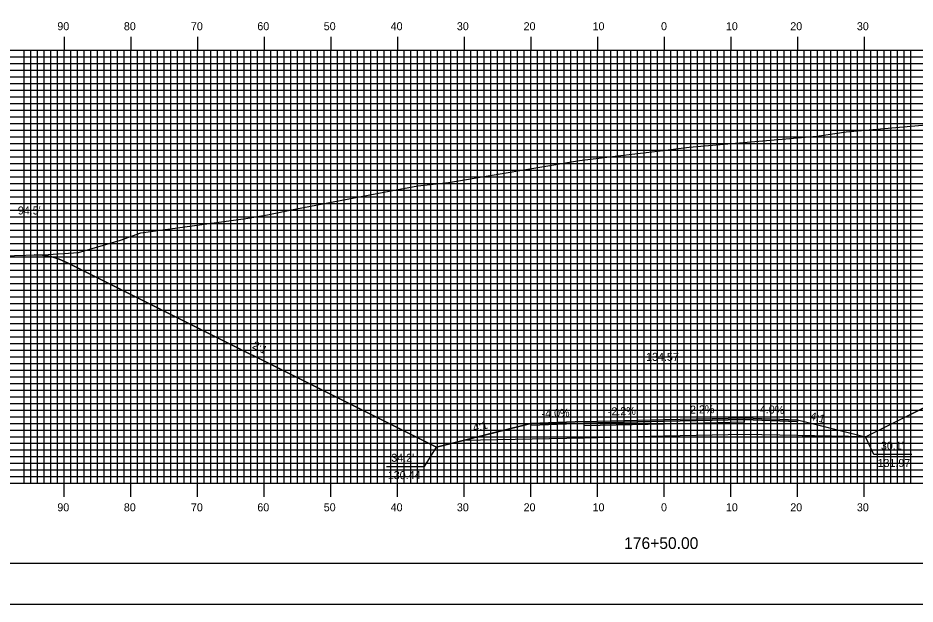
# Model space of a CAD drawing. Extents: x 1784615 to 1784958, y 442591 to 442811.
# Drawn here: x 1784683.6 to 1784818.1, y 442590.5 to 442678.5 of the extents above; entities that cross this region are included whole.
import ezdxf

# ---------------------------------------------------------------- set-up
doc = ezdxf.new("R2010")
doc.units = 0
for name, color, linetype in [('ANNOTATION', 7, 'Continuous'), ('BORDER', 7, 'Continuous'), ('D_Roadway_Centerline', 7, 'Continuous'), ('D_Roadway_Centerline_Text', 7, 'Continuous'), ('D_Roadway_Edge_Shoulder', 7, 'Continuous'), ('D_Roadway_Edge_TW', 7, 'Continuous'), ('D_Roadway_Pavement', 7, 'Continuous'), ('D_Roadway_SlopeLines', 7, 'Continuous'), ('D_Roadway_SubGrade', 7, 'Continuous'), ('D_Text_Standard', 7, 'Continuous'), ('H_V ANNOTATION', 7, 'Continuous'), ('MAJOR', 7, 'Continuous'), ('MINOR', 7, 'Continuous'), ('PLOT BOUNDARY', 7, 'Continuous'), ('S_Roadway_Centerline', 7, 'Continuous')]:
    doc.layers.add(name, color=color, linetype=linetype)

msp = doc.modelspace()

# ---------------------------------------------------------------- linework, layer by layer
at = {"layer": 'ANNOTATION'}
for points in [[(1784817.65, 442613), (1784811.96, 442613), (1784810.69, 442615.64)], [(1784738.83, 442611.17), (1784744.53, 442611.17), (1784746.34, 442614.11)]]:
    msp.add_lwpolyline(points, dxfattribs=at)
at = {"layer": 'BORDER'}
msp.add_lwpolyline([(1784630.91, 442596.67), (1784950.91, 442596.67), (1784950.91, 442806.67), (1784630.91, 442806.67)], close=True, dxfattribs=at)
at = {"layer": 'D_Roadway_Centerline'}
msp.add_lwpolyline([(1784685.99, 442642.94), (1784687.24, 442642.9), (1784688.49, 442642.7), (1784689.74, 442642.32), (1784690.99, 442641.78), (1784746.34, 442614.11), (1784750.34, 442615.11), (1784760.51, 442617.65), (1784768.51, 442617.97), (1784780.51, 442618.24), (1784792.51, 442618.5), (1784800.51, 442618.18), (1784810.69, 442615.64), (1784902.15, 442661.37)], dxfattribs=at)
at = {"layer": 'D_Roadway_Edge_Shoulder'}
for points in [[(1784768.51, 442617.97), (1784760.51, 442617.65), (1784760.51, 442617.4), (1784768.51, 442617.72)], [(1784792.51, 442618.5), (1784800.51, 442618.18), (1784800.51, 442617.93), (1784792.51, 442618.25)]]:
    msp.add_lwpolyline(points, close=True, dxfattribs=at)
at = {"layer": 'D_Roadway_Edge_TW'}
msp.add_lwpolyline([(1784768.51, 442617.72), (1784768.51, 442617.97), (1784780.51, 442618.24), (1784792.51, 442618.5), (1784792.51, 442618.25), (1784780.51, 442617.99)], close=True, dxfattribs=at)
at = {"layer": 'D_Roadway_Pavement'}
msp.add_lwpolyline([(1784768.51, 442617.3), (1784768.51, 442617.72), (1784780.51, 442617.99), (1784792.51, 442618.25), (1784792.51, 442617.83), (1784780.51, 442617.57)], close=True, dxfattribs=at)
at = {"layer": 'D_Roadway_SlopeLines'}
for p, q in [((1784812.69, 442616.64), (1784902.15, 442661.37)), ((1784800.51, 442618.18), (1784810.69, 442615.64)), ((1784810.69, 442615.64), (1784812.69, 442616.64)), ((1784801.22, 442615.83), (1784810.69, 442615.64))]:
    msp.add_line(p, q, dxfattribs=at)
for points in [[(1784746.34, 442614.11), (1784690.99, 442641.78), (1784689.74, 442642.32), (1784688.49, 442642.7), (1784687.24, 442642.9), (1784685.99, 442642.94)], [(1784800.51, 442618.18), (1784805.13, 442617.03)], [(1784760.51, 442617.65), (1784746.34, 442614.11)]]:
    msp.add_lwpolyline(points, dxfattribs=at)
at = {"layer": 'D_Roadway_SubGrade'}
msp.add_lwpolyline([(1784768.51, 442615.47), (1784750.34, 442615.11), (1784760.51, 442617.65), (1784760.51, 442617.4), (1784768.51, 442617.72), (1784780.51, 442617.99), (1784792.51, 442618.25), (1784800.51, 442617.93), (1784800.51, 442618.18), (1784810.69, 442615.64), (1784800.51, 442615.84), (1784792.51, 442616), (1784780.51, 442615.74)], close=True, dxfattribs=at)
at = {"layer": 'MAJOR'}
for p, q in [((1784690.51, 442675.67), (1784690.51, 442673.67)), ((1784700.51, 442675.67), (1784700.51, 442673.67)), ((1784710.51, 442675.67), (1784710.51, 442673.67)), ((1784720.51, 442675.67), (1784720.51, 442673.67)), ((1784730.51, 442675.67), (1784730.51, 442673.67)), ((1784740.51, 442675.67), (1784740.51, 442673.67)), ((1784750.51, 442675.67), (1784750.51, 442673.67)), ((1784760.51, 442675.67), (1784760.51, 442673.67)), ((1784770.51, 442675.67), (1784770.51, 442673.67)), ((1784780.51, 442675.67), (1784780.51, 442673.67)), ((1784790.51, 442675.67), (1784790.51, 442673.67)), ((1784800.51, 442675.67), (1784800.51, 442673.67)), ((1784810.51, 442675.67), (1784810.51, 442673.67)), ((1784640.51, 442673.67), (1784920.51, 442673.67)), ((1784640.51, 442673.67), (1784920.51, 442673.67)), ((1784690.51, 442608.67), (1784690.51, 442673.67)), ((1784700.51, 442608.67), (1784700.51, 442673.67)), ((1784710.51, 442608.67), (1784710.51, 442673.67)), ((1784720.51, 442608.67), (1784720.51, 442673.67)), ((1784730.51, 442608.67), (1784730.51, 442673.67)), ((1784740.51, 442608.67), (1784740.51, 442673.67)), ((1784750.51, 442608.67), (1784750.51, 442673.67)), ((1784760.51, 442608.67), (1784760.51, 442673.67)), ((1784770.51, 442608.67), (1784770.51, 442673.67)), ((1784780.51, 442608.67), (1784780.51, 442673.67)), ((1784790.51, 442608.67), (1784790.51, 442673.67)), ((1784800.51, 442608.67), (1784800.51, 442673.67)), ((1784810.51, 442608.67), (1784810.51, 442673.67)), ((1784640.51, 442668.67), (1784920.51, 442668.67)), ((1784640.51, 442663.67), (1784920.51, 442663.67)), ((1784640.51, 442658.67), (1784920.51, 442658.67)), ((1784640.51, 442653.67), (1784920.51, 442653.67)), ((1784640.51, 442648.67), (1784920.51, 442648.67)), ((1784640.51, 442643.67), (1784920.51, 442643.67)), ((1784640.51, 442638.67), (1784920.51, 442638.67)), ((1784640.51, 442633.67), (1784920.51, 442633.67)), ((1784640.51, 442628.67), (1784920.51, 442628.67)), ((1784640.51, 442623.67), (1784920.51, 442623.67)), ((1784640.51, 442618.67), (1784920.51, 442618.67)), ((1784640.51, 442613.67), (1784920.51, 442613.67)), ((1784640.51, 442608.67), (1784920.51, 442608.67)), ((1784690.51, 442606.66), (1784690.51, 442608.67)), ((1784700.51, 442606.66), (1784700.51, 442608.67)), ((1784710.51, 442606.66), (1784710.51, 442608.67)), ((1784720.51, 442606.66), (1784720.51, 442608.67)), ((1784730.51, 442606.66), (1784730.51, 442608.67)), ((1784740.51, 442606.66), (1784740.51, 442608.67)), ((1784750.51, 442606.66), (1784750.51, 442608.67)), ((1784760.51, 442606.66), (1784760.51, 442608.67)), ((1784770.51, 442606.66), (1784770.51, 442608.67)), ((1784780.51, 442606.66), (1784780.51, 442608.67)), ((1784790.51, 442606.66), (1784790.51, 442608.67)), ((1784800.51, 442606.66), (1784800.51, 442608.67)), ((1784810.51, 442606.66), (1784810.51, 442608.67))]:
    msp.add_line(p, q, dxfattribs=at)
at = {"layer": 'MINOR'}
for p, q in [((1784684.51, 442608.67), (1784684.51, 442673.67)), ((1784685.51, 442608.67), (1784685.51, 442673.67)), ((1784686.51, 442608.67), (1784686.51, 442673.67)), ((1784687.51, 442608.67), (1784687.51, 442673.67)), ((1784688.51, 442608.67), (1784688.51, 442673.67)), ((1784689.51, 442608.67), (1784689.51, 442673.67)), ((1784691.51, 442608.67), (1784691.51, 442673.67)), ((1784692.51, 442608.67), (1784692.51, 442673.67)), ((1784693.51, 442608.67), (1784693.51, 442673.67)), ((1784694.51, 442608.67), (1784694.51, 442673.67)), ((1784695.51, 442608.67), (1784695.51, 442673.67)), ((1784696.51, 442608.67), (1784696.51, 442673.67)), ((1784697.51, 442608.67), (1784697.51, 442673.67)), ((1784698.51, 442608.67), (1784698.51, 442673.67)), ((1784699.51, 442608.67), (1784699.51, 442673.67)), ((1784701.51, 442608.67), (1784701.51, 442673.67)), ((1784702.51, 442608.67), (1784702.51, 442673.67)), ((1784703.51, 442608.67), (1784703.51, 442673.67)), ((1784704.51, 442608.67), (1784704.51, 442673.67)), ((1784705.51, 442608.67), (1784705.51, 442673.67)), ((1784706.51, 442608.67), (1784706.51, 442673.67)), ((1784707.51, 442608.67), (1784707.51, 442673.67)), ((1784708.51, 442608.67), (1784708.51, 442673.67)), ((1784709.51, 442608.67), (1784709.51, 442673.67)), ((1784711.51, 442608.67), (1784711.51, 442673.67)), ((1784712.51, 442608.67), (1784712.51, 442673.67)), ((1784713.51, 442608.67), (1784713.51, 442673.67)), ((1784714.51, 442608.67), (1784714.51, 442673.67)), ((1784715.51, 442608.67), (1784715.51, 442673.67)), ((1784716.51, 442608.67), (1784716.51, 442673.67)), ((1784717.51, 442608.67), (1784717.51, 442673.67)), ((1784718.51, 442608.67), (1784718.51, 442673.67)), ((1784719.51, 442608.67), (1784719.51, 442673.67)), ((1784721.51, 442608.67), (1784721.51, 442673.67)), ((1784722.51, 442608.67), (1784722.51, 442673.67)), ((1784723.51, 442608.67), (1784723.51, 442673.67)), ((1784724.51, 442608.67), (1784724.51, 442673.67)), ((1784725.51, 442608.67), (1784725.51, 442673.67)), ((1784726.51, 442608.67), (1784726.51, 442673.67)), ((1784727.51, 442608.67), (1784727.51, 442673.67)), ((1784728.51, 442608.67), (1784728.51, 442673.67)), ((1784729.51, 442608.67), (1784729.51, 442673.67)), ((1784731.51, 442608.67), (1784731.51, 442673.67)), ((1784732.51, 442608.67), (1784732.51, 442673.67)), ((1784733.51, 442608.67), (1784733.51, 442673.67)), ((1784734.51, 442608.67), (1784734.51, 442673.67)), ((1784735.51, 442608.67), (1784735.51, 442673.67)), ((1784736.51, 442608.67), (1784736.51, 442673.67)), ((1784737.51, 442608.67), (1784737.51, 442673.67)), ((1784738.51, 442608.67), (1784738.51, 442673.67)), ((1784739.51, 442608.67), (1784739.51, 442673.67)), ((1784741.51, 442608.67), (1784741.51, 442673.67)), ((1784742.51, 442608.67), (1784742.51, 442673.67)), ((1784743.51, 442608.67), (1784743.51, 442673.67)), ((1784744.51, 442608.67), (1784744.51, 442673.67)), ((1784745.51, 442608.67), (1784745.51, 442673.67)), ((1784746.51, 442608.67), (1784746.51, 442673.67)), ((1784747.51, 442608.67), (1784747.51, 442673.67)), ((1784748.51, 442608.67), (1784748.51, 442673.67)), ((1784749.51, 442608.67), (1784749.51, 442673.67)), ((1784751.51, 442608.67), (1784751.51, 442673.67)), ((1784752.51, 442608.67), (1784752.51, 442673.67)), ((1784753.51, 442608.67), (1784753.51, 442673.67)), ((1784754.51, 442608.67), (1784754.51, 442673.67)), ((1784755.51, 442608.67), (1784755.51, 442673.67)), ((1784756.51, 442608.67), (1784756.51, 442673.67)), ((1784757.51, 442608.67), (1784757.51, 442673.67)), ((1784758.51, 442608.67), (1784758.51, 442673.67)), ((1784759.51, 442608.67), (1784759.51, 442673.67)), ((1784761.51, 442608.67), (1784761.51, 442673.67)), ((1784762.51, 442608.67), (1784762.51, 442673.67)), ((1784763.51, 442608.67), (1784763.51, 442673.67)), ((1784764.51, 442608.67), (1784764.51, 442673.67)), ((1784765.51, 442608.67), (1784765.51, 442673.67)), ((1784766.51, 442608.67), (1784766.51, 442673.67)), ((1784767.51, 442608.67), (1784767.51, 442673.67)), ((1784768.51, 442608.67), (1784768.51, 442673.67)), ((1784769.51, 442608.67), (1784769.51, 442673.67)), ((1784771.51, 442608.67), (1784771.51, 442673.67)), ((1784772.51, 442608.67), (1784772.51, 442673.67)), ((1784773.51, 442608.67), (1784773.51, 442673.67)), ((1784774.51, 442608.67), (1784774.51, 442673.67)), ((1784775.51, 442608.67), (1784775.51, 442673.67)), ((1784776.51, 442608.67), (1784776.51, 442673.67)), ((1784777.51, 442608.67), (1784777.51, 442673.67)), ((1784778.51, 442608.67), (1784778.51, 442673.67)), ((1784779.51, 442608.67), (1784779.51, 442673.67)), ((1784781.51, 442608.67), (1784781.51, 442673.67)), ((1784782.51, 442608.67), (1784782.51, 442673.67)), ((1784783.51, 442608.67), (1784783.51, 442673.67)), ((1784784.51, 442608.67), (1784784.51, 442673.67)), ((1784785.51, 442608.67), (1784785.51, 442673.67)), ((1784786.51, 442608.67), (1784786.51, 442673.67)), ((1784787.51, 442608.67), (1784787.51, 442673.67)), ((1784788.51, 442608.67), (1784788.51, 442673.67)), ((1784789.51, 442608.67), (1784789.51, 442673.67)), ((1784791.51, 442608.67), (1784791.51, 442673.67)), ((1784792.51, 442608.67), (1784792.51, 442673.67)), ((1784793.51, 442608.67), (1784793.51, 442673.67)), ((1784794.51, 442608.67), (1784794.51, 442673.67)), ((1784795.51, 442608.67), (1784795.51, 442673.67)), ((1784796.51, 442608.67), (1784796.51, 442673.67)), ((1784797.51, 442608.67), (1784797.51, 442673.67)), ((1784798.51, 442608.67), (1784798.51, 442673.67)), ((1784799.51, 442608.67), (1784799.51, 442673.67)), ((1784801.51, 442608.67), (1784801.51, 442673.67)), ((1784802.51, 442608.67), (1784802.51, 442673.67)), ((1784803.51, 442608.67), (1784803.51, 442673.67)), ((1784804.51, 442608.67), (1784804.51, 442673.67)), ((1784805.51, 442608.67), (1784805.51, 442673.67)), ((1784806.51, 442608.67), (1784806.51, 442673.67)), ((1784807.51, 442608.67), (1784807.51, 442673.67)), ((1784808.51, 442608.67), (1784808.51, 442673.67)), ((1784809.51, 442608.67), (1784809.51, 442673.67)), ((1784811.51, 442608.67), (1784811.51, 442673.67)), ((1784812.51, 442608.67), (1784812.51, 442673.67)), ((1784813.51, 442608.67), (1784813.51, 442673.67)), ((1784814.51, 442608.67), (1784814.51, 442673.67)), ((1784815.51, 442608.67), (1784815.51, 442673.67)), ((1784816.51, 442608.67), (1784816.51, 442673.67)), ((1784817.51, 442608.67), (1784817.51, 442673.67)), ((1784640.51, 442672.67), (1784920.51, 442672.67)), ((1784640.51, 442671.67), (1784920.51, 442671.67)), ((1784640.51, 442670.67), (1784920.51, 442670.67)), ((1784640.51, 442669.67), (1784920.51, 442669.67)), ((1784640.51, 442667.67), (1784920.51, 442667.67)), ((1784640.51, 442666.67), (1784920.51, 442666.67)), ((1784640.51, 442665.67), (1784920.51, 442665.67)), ((1784640.51, 442664.67), (1784920.51, 442664.67)), ((1784640.51, 442662.67), (1784920.51, 442662.67)), ((1784640.51, 442661.67), (1784920.51, 442661.67)), ((1784640.51, 442660.67), (1784920.51, 442660.67)), ((1784640.51, 442659.67), (1784920.51, 442659.67)), ((1784640.51, 442657.67), (1784920.51, 442657.67)), ((1784640.51, 442656.67), (1784920.51, 442656.67)), ((1784640.51, 442655.67), (1784920.51, 442655.67)), ((1784640.51, 442654.67), (1784920.51, 442654.67)), ((1784640.51, 442652.67), (1784920.51, 442652.67)), ((1784640.51, 442651.67), (1784920.51, 442651.67)), ((1784640.51, 442650.67), (1784920.51, 442650.67)), ((1784640.51, 442649.67), (1784920.51, 442649.67)), ((1784640.51, 442647.67), (1784920.51, 442647.67)), ((1784640.51, 442646.67), (1784920.51, 442646.67)), ((1784640.51, 442645.67), (1784920.51, 442645.67)), ((1784640.51, 442644.67), (1784920.51, 442644.67)), ((1784640.51, 442642.67), (1784920.51, 442642.67)), ((1784640.51, 442641.67), (1784920.51, 442641.67)), ((1784640.51, 442640.67), (1784920.51, 442640.67)), ((1784640.51, 442639.67), (1784920.51, 442639.67)), ((1784640.51, 442637.67), (1784920.51, 442637.67)), ((1784640.51, 442636.67), (1784920.51, 442636.67)), ((1784640.51, 442635.67), (1784920.51, 442635.67)), ((1784640.51, 442634.67), (1784920.51, 442634.67)), ((1784640.51, 442632.67), (1784920.51, 442632.67)), ((1784640.51, 442631.67), (1784920.51, 442631.67)), ((1784640.51, 442630.67), (1784920.51, 442630.67)), ((1784640.51, 442629.67), (1784920.51, 442629.67)), ((1784640.51, 442627.67), (1784920.51, 442627.67)), ((1784640.51, 442626.67), (1784920.51, 442626.67)), ((1784640.51, 442625.67), (1784920.51, 442625.67)), ((1784640.51, 442624.67), (1784920.51, 442624.67)), ((1784640.51, 442622.67), (1784920.51, 442622.67)), ((1784640.51, 442621.67), (1784920.51, 442621.67)), ((1784640.51, 442620.67), (1784920.51, 442620.67)), ((1784640.51, 442619.67), (1784920.51, 442619.67)), ((1784640.51, 442617.67), (1784920.51, 442617.67)), ((1784640.51, 442616.67), (1784920.51, 442616.67)), ((1784640.51, 442615.67), (1784920.51, 442615.67)), ((1784640.51, 442614.67), (1784920.51, 442614.67)), ((1784640.51, 442612.67), (1784920.51, 442612.67)), ((1784640.51, 442611.67), (1784920.51, 442611.67)), ((1784640.51, 442610.67), (1784920.51, 442610.67)), ((1784640.51, 442609.67), (1784920.51, 442609.67))]:
    msp.add_line(p, q, dxfattribs=at)
at = {"layer": 'PLOT BOUNDARY'}
msp.add_lwpolyline([(1784614.73, 442590.55), (1784954.73, 442590.55), (1784954.73, 442810.55), (1784614.73, 442810.55)], close=True, dxfattribs=at)
at = {"layer": 'S_Roadway_Centerline'}
msp.add_lwpolyline([(1784681.37, 442642.79), (1784688.11, 442643), (1784692.65, 442643.32), (1784698.98, 442645.18), (1784702, 442646.28), (1784717.77, 442648.43), (1784720.98, 442648.95), (1784725.1, 442649.79), (1784739.5, 442652.58), (1784743.57, 442653.31), (1784748.13, 442653.84), (1784767.78, 442657.1), (1784774.41, 442657.93), (1784779.5, 442658.54), (1784784.27, 442659.12), (1784803.42, 442660.79), (1784807.8, 442661.4), (1784823.23, 442662.76)], dxfattribs=at)

# ---------------------------------------------------------------- texts
at = {"layer": 'ANNOTATION'}
for s, rotation, p in [('2:1', 333.4349, (1784718.6, 442629.01)), ('-4.0%', 2.2906, (1784762.14, 442618.52)), ('-2.2%', 1.2603, (1784772.07, 442618.85)), ('2.2%', 1.2603, (1784784.39, 442619.12)), ('-4.0%', 357.7094, (1784794.3, 442619.23)), ('4:1', 345.9638, (1784802.3, 442618.24)), ('4:1', 14.0362, (1784751.96, 442616.38))]:
    msp.add_text(s, height=1.2, rotation=rotation, dxfattribs=at).set_placement(p)
for s, p in [("30.1'", (1784813.01, 442613.72)), ("34.2'", (1784739.57, 442611.9)), ('131.97', (1784812.51, 442611.12)), ('130.44', (1784739.05, 442609.3))]:
    msp.add_text(s, height=1.2, dxfattribs=at).set_placement(p)
at = {"layer": 'D_Roadway_Centerline'}
for s, p in [('C', (1784780.51, 442618.24)), ('L', (1784780.51, 442618.23))]:
    msp.add_text(s, height=0.0146, dxfattribs=at).set_placement(p)
at = {"layer": 'D_Roadway_Centerline_Text'}
msp.add_text('134.57', height=1.2, dxfattribs=at).set_placement((1784777.79, 442627.05))
at = {"layer": 'D_Text_Standard'}
msp.add_text("94.5'", height=1.2, dxfattribs=at).set_placement((1784683.56, 442649.02))
at = {"layer": 'H_V ANNOTATION'}
for s, height, p in [('90', 1.2, (1784689.48, 442676.67)), ('80', 1.2, (1784699.46, 442676.67)), ('70', 1.2, (1784709.52, 442676.67)), ('60', 1.2, (1784719.48, 442676.67)), ('50', 1.2, (1784729.44, 442676.67)), ('40', 1.2, (1784739.48, 442676.67)), ('30', 1.2, (1784749.41, 442676.67)), ('20', 1.2, (1784759.42, 442676.67)), ('10', 1.2, (1784769.76, 442676.67)), ('0', 1.2, (1784780.03, 442676.67)), ('10', 1.2, (1784789.76, 442676.67)), ('20', 1.2, (1784799.42, 442676.67)), ('30', 1.2, (1784809.41, 442676.67)), ('90', 1.2, (1784689.48, 442604.47)), ('80', 1.2, (1784699.46, 442604.47)), ('70', 1.2, (1784709.52, 442604.47)), ('60', 1.2, (1784719.48, 442604.47)), ('50', 1.2, (1784729.44, 442604.47)), ('40', 1.2, (1784739.48, 442604.47)), ('30', 1.2, (1784749.41, 442604.47)), ('20', 1.2, (1784759.42, 442604.47)), ('10', 1.2, (1784769.76, 442604.47)), ('0', 1.2, (1784780.03, 442604.47)), ('10', 1.2, (1784789.76, 442604.47)), ('20', 1.2, (1784799.42, 442604.47)), ('30', 1.2, (1784809.41, 442604.47)), ('176+50.00', 1.75, (1784774.5, 442598.82))]:
    msp.add_text(s, height=height, dxfattribs=at).set_placement(p)

doc.saveas('drawing.dxf')
